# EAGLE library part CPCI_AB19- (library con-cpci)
Compact PCI AB 19 Source: www.erni.com
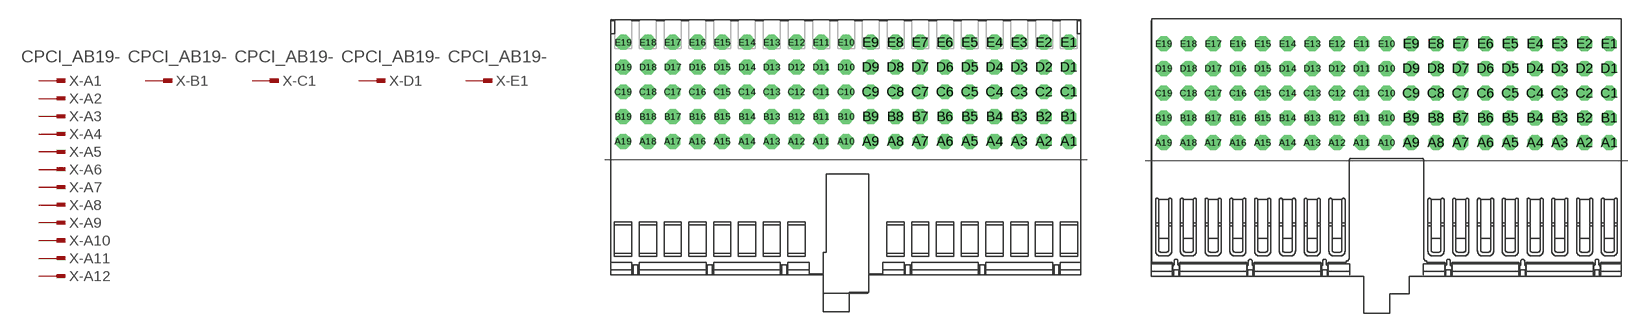
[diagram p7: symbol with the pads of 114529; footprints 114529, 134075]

Designator prefix X; gates -A1=PINV -B1=PINV -C1=PINV -D1=PINV -E1=PINV -A2=PIN -A3=PIN -A4=PIN -A5=PIN -A6=PIN -A7=PIN -A8=PIN -A9=PIN -A10=PIN -A11=PIN -A12=PIN -A13=PIN -A14=PIN -A15=PIN -A16=PIN -A17=PIN -A18=PIN -A19=PIN -B2=PIN -B3=PIN -B4=PIN -B5=PIN -B6=PIN -B7=PIN -B8=PIN -B9=PIN -B10=PIN -B11=PIN -B12=PIN -B13=PIN -B14=PIN -B15=PIN -B16=PIN -B17=PIN -B18=PIN -B19=PIN -C2=PIN -C3=PIN -C4=PIN -C5=PIN -C6=PIN -C7=PIN -C8=PIN -C9=PIN -C10=PIN -C11=PIN -C12=PIN -C13=PIN -C14=PIN -C15=PIN -C16=PIN -C17=PIN -C18=PIN -C19=PIN -D2=PIN -D3=PIN -D4=PIN -D5=PIN -D6=PIN -D7=PIN -D8=PIN -D9=PIN -D10=PIN -D11=PIN -D12=PIN -D13=PIN -D14=PIN -D15=PIN -D16=PIN -D17=PIN -D18=PIN -D19=PIN -E2=PIN -E3=PIN -E4=PIN -E5=PIN -E6=PIN -E7=PIN -E8=PIN -E9=PIN -E10=PIN -E11=PIN -E12=PIN -E13=PIN -E14=PIN -E15=PIN -E16=PIN -E17=PIN -E18=PIN -E19=PIN

## CPCI_AB19-114529  [114529]
A1  -A1:1  in
A2  -A2:1  in
A3  -A3:1  in
A4  -A4:1  in
A5  -A5:1  in
A6  -A6:1  in
A7  -A7:1  in
A8  -A8:1  in
A9  -A9:1  in
A10  -A10:1  in
A11  -A11:1  in
A12  -A12:1  in
A13  -A13:1  in
A14  -A14:1  in
A15  -A15:1  in
A16  -A16:1  in
A17  -A17:1  in
A18  -A18:1  in
A19  -A19:1  in
B1  -B1:1  in
B2  -B2:1  in
B3  -B3:1  in
B4  -B4:1  in
B5  -B5:1  in
B6  -B6:1  in
B7  -B7:1  in
B8  -B8:1  in
B9  -B9:1  in
B10  -B10:1  in
B11  -B11:1  in
B12  -B12:1  in
B13  -B13:1  in
B14  -B14:1  in
B15  -B15:1  in
B16  -B16:1  in
B17  -B17:1  in
B18  -B18:1  in
B19  -B19:1  in
C1  -C1:1  in
C2  -C2:1  in
C3  -C3:1  in
C4  -C4:1  in
C5  -C5:1  in
C6  -C6:1  in
C7  -C7:1  in
C8  -C8:1  in
C9  -C9:1  in
C10  -C10:1  in
C11  -C11:1  in
C12  -C12:1  in
C13  -C13:1  in
C14  -C14:1  in
C15  -C15:1  in
C16  -C16:1  in
C17  -C17:1  in
C18  -C18:1  in
C19  -C19:1  in
D1  -D1:1  in
D2  -D2:1  in
D3  -D3:1  in
D4  -D4:1  in
D5  -D5:1  in
D6  -D6:1  in
D7  -D7:1  in
D8  -D8:1  in
D9  -D9:1  in
D10  -D10:1  in
D11  -D11:1  in
D12  -D12:1  in
D13  -D13:1  in
D14  -D14:1  in
D15  -D15:1  in
D16  -D16:1  in
D17  -D17:1  in
D18  -D18:1  in
D19  -D19:1  in
E1  -E1:1  in
E2  -E2:1  in
E3  -E3:1  in
E4  -E4:1  in
E5  -E5:1  in
E6  -E6:1  in
E7  -E7:1  in
E8  -E8:1  in
E9  -E9:1  in
E10  -E10:1  in
E11  -E11:1  in
E12  -E12:1  in
E13  -E13:1  in
E14  -E14:1  in
E15  -E15:1  in
E16  -E16:1  in
E17  -E17:1  in
E18  -E18:1  in
E19  -E19:1  in

## CPCI_AB19-134075  [134075]
Pads as for 114529

## Footprint 114529 (pad centres in mm)
ERmet Federleiste AB 19 / ERmet Female Type AB 19 Source: http://www.erni.com/DB/PDF-Drawing/ERmet/114529.pdf
drill 0.7 pad 1.016 octagon: A1 18,1.5; A2 16,1.5; A3 14,1.5; A4 12,1.5; A5 10,1.5; A6 8,1.5; A7 6,1.5; A8 4,1.5; A9 2,1.5; A10 0,1.5; A11 -2,1.5; A12 -4,1.5; A13 -6,1.5; A14 -8,1.5; A15 -10,1.5; A16 -12,1.5; A17 -14,1.5; A18 -16,1.5; A19 -18,1.5; B1 18,3.5; B2 16,3.5; B3 14,3.5; B4 12,3.5; B5 10,3.5; B6 8,3.5; B7 6,3.5; B8 4,3.5; B9 2,3.5; B10 0,3.5; B11 -2,3.5; B12 -4,3.5; B13 -6,3.5; B14 -8,3.5; B15 -10,3.5; B16 -12,3.5; B17 -14,3.5; B18 -16,3.5; B19 -18,3.5; C1 18,5.5; C2 16,5.5; C3 14,5.5; C4 12,5.5; C5 10,5.5; C6 8,5.5; C7 6,5.5; C8 4,5.5; C9 2,5.5; C10 0,5.5; C11 -2,5.5; C12 -4,5.5; C13 -6,5.5; C14 -8,5.5; C15 -10,5.5; C16 -12,5.5; C17 -14,5.5; C18 -16,5.5; C19 -18,5.5; D1 18,7.5; D2 16,7.5; D3 14,7.5; D4 12,7.5; D5 10,7.5; D6 8,7.5; D7 6,7.5; D8 4,7.5; D9 2,7.5; D10 0,7.5; D11 -2,7.5; D12 -4,7.5; D13 -6,7.5; D14 -8,7.5; D15 -10,7.5; D16 -12,7.5; D17 -14,7.5; D18 -16,7.5; D19 -18,7.5; E1 18,9.5; E2 16,9.5; E3 14,9.5; E4 12,9.5; E5 10,9.5; E6 8,9.5; E7 6,9.5; E8 4,9.5; E9 2,9.5; E10 0,9.5; E11 -2,9.5; E12 -4,9.5; E13 -6,9.5; E14 -8,9.5; E15 -10,9.5; E16 -12,9.5; E17 -14,9.5; E18 -16,9.5; E19 -18,9.5

## Footprint 134075 (pad centres in mm)
ERmet Federleiste AB 19 / ERmet Female Type AB 19 Source: http://www.erni.com/DB/PDF-Drawing/ERmet/134075.pdf
drill 0.7 pad 1.016 octagon: A1 77,56.5; A2 75,56.5; A3 73,56.5; A4 71,56.5; A5 69,56.5; A6 67,56.5; A7 65,56.5; A8 63,56.5; A9 61,56.5; A10 59,56.5; A11 57,56.5; A12 55,56.5; A13 53,56.5; A14 51,56.5; A15 49,56.5; A16 47,56.5; A17 45,56.5; A18 43,56.5; A19 41,56.5; B1 77,58.5; B2 75,58.5; B3 73,58.5; B4 71,58.5; B5 69,58.5; B6 67,58.5; B7 65,58.5; B8 63,58.5; B9 61,58.5; B10 59,58.5; B11 57,58.5; B12 55,58.5; B13 53,58.5; B14 51,58.5; B15 49,58.5; B16 47,58.5; B17 45,58.5; B18 43,58.5; B19 41,58.5; C1 77,60.5; C2 75,60.5; C3 73,60.5; C4 71,60.5; C5 69,60.5; C6 67,60.5; C7 65,60.5; C8 63,60.5; C9 61,60.5; C10 59,60.5; C11 57,60.5; C12 55,60.5; C13 53,60.5; C14 51,60.5; C15 49,60.5; C16 47,60.5; C17 45,60.5; C18 43,60.5; C19 41,60.5; D1 77,62.5; D2 75,62.5; D3 73,62.5; D4 71,62.5; D5 69,62.5; D6 67,62.5; D7 65,62.5; D8 63,62.5; D9 61,62.5; D10 59,62.5; D11 57,62.5; D12 55,62.5; D13 53,62.5; D14 51,62.5; D15 49,62.5; D16 47,62.5; D17 45,62.5; D18 43,62.5; D19 41,62.5; E1 77,64.5; E2 75,64.5; E3 73,64.5; E4 71,64.5; E5 69,64.5; E6 67,64.5; E7 65,64.5; E8 63,64.5; E9 61,64.5; E10 59,64.5; E11 57,64.5; E12 55,64.5; E13 53,64.5; E14 51,64.5; E15 49,64.5; E16 47,64.5; E17 45,64.5; E18 43,64.5; E19 41,64.5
